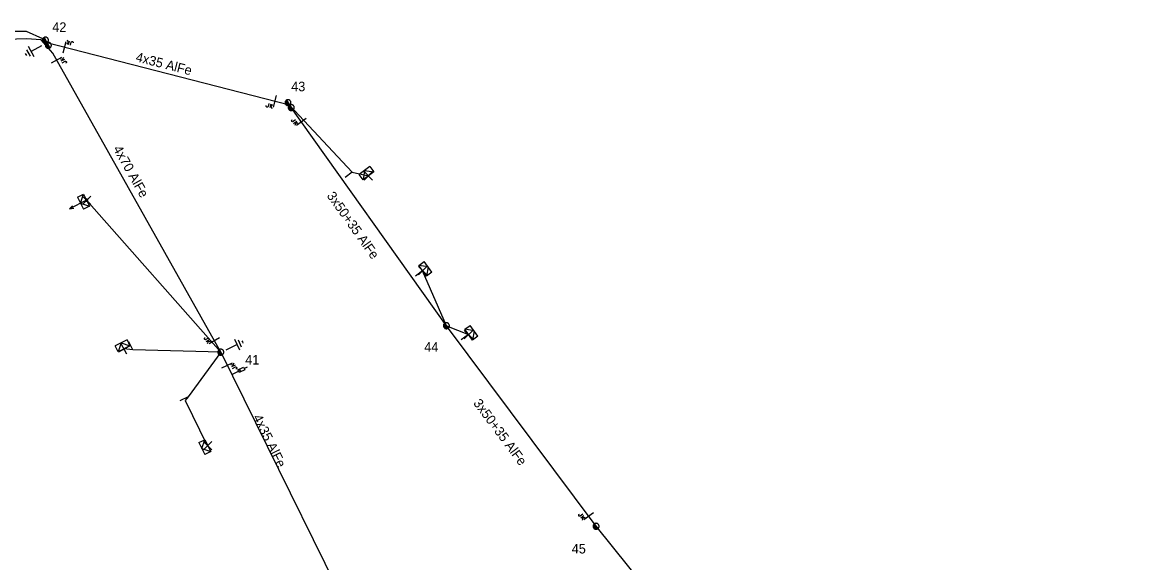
# Model space of a CAD drawing. Extents: x -536148 to -535465, y -1201639 to -1201298.
# Drawn here: x -535725.2 to -535608.3, y -1201357.9 to -1201301.1 of the extents above; entities that cross this region are included whole.
import ezdxf

# ---------------------------------------------------------------- set-up
doc = ezdxf.new("R2010")
doc.units = 0
for name, color, linetype in [('CIZÍ_NADZEM_POPIS', 7, 'Continuous'), ('CIZÍ_PODZEM', 7, 'Continuous'), ('DOPLŇ_POPISY', 7, 'Continuous'), ('ELE_EON', 7, 'Continuous'), ('ELE_EON_POPIS', 7, 'Continuous'), ('KN_HRAN_POHYBLIVÁ', 7, 'Continuous'), ('KN_HRAN_STÁTNÍ', 7, 'Continuous'), ('KN_VKP_HRAN_NEZNATELNÁ', 7, 'Continuous'), ('KN_VKP_HRAN_SPORNÁ', 7, 'Continuous'), ('NADZEM_NN_IZOL_POPIS', 7, 'Continuous'), ('PB_NN_POPIS', 7, 'Continuous'), ('PLG_EXPORT_GPE', 7, 'Continuous'), ('PROJEKT', 7, 'Continuous'), ('RÁMEČEK', 7, 'Continuous')]:
    doc.layers.add(name, color=color, linetype=linetype)

# ---------------------------------------------------------------- blocks, each defined once
blk = doc.blocks.new('NN440')
at = {"layer": 'ELE_EON_POPIS'}
for points in [[(0.63, 0), (0.63, 0.06), (0.62, 0.13), (0.6, 0.19), (0.58, 0.25), (0.55, 0.31), (0.51, 0.37), (0.47, 0.42), (0.42, 0.46), (0.37, 0.51), (0.32, 0.54), (0.26, 0.57), (0.2, 0.59), (0.13, 0.61), (0.07, 0.62), (0, 0.63), (-0.06, 0.62), (-0.13, 0.61), (-0.19, 0.59), (-0.26, 0.57), (-0.31, 0.54), (-0.37, 0.51), (-0.42, 0.46), (-0.47, 0.42), (-0.51, 0.37), (-0.54, 0.31), (-0.57, 0.25), (-0.6, 0.19), (-0.62, 0.13), (-0.63, 0.06), (-0.63, 0), (-0.63, -0.07), (-0.62, -0.14), (-0.6, -0.2), (-0.57, -0.26), (-0.54, -0.32), (-0.51, -0.37), (-0.47, -0.43), (-0.42, -0.47), (-0.37, -0.51), (-0.31, -0.55), (-0.26, -0.58), (-0.19, -0.6), (-0.13, -0.62), (-0.06, -0.63), (0, -0.63), (0.07, -0.63), (0.13, -0.62), (0.2, -0.6), (0.26, -0.58), (0.32, -0.55), (0.37, -0.51), (0.42, -0.47), (0.47, -0.43), (0.51, -0.37), (0.55, -0.32), (0.58, -0.26), (0.6, -0.2), (0.62, -0.14), (0.63, -0.07), (0.63, 0)], [(-0.63, 0), (0.63, 0)], [(-0.6, -0.18), (0.57, -0.18)], [(-0.51, -0.32), (0.5, -0.32)], [(-0.37, -0.47), (0.35, -0.47)]]:
    blk.add_lwpolyline(points, dxfattribs=at)
blk = doc.blocks.new('NN450')
at = {"layer": 'ELE_EON_POPIS'}
for points in [[(0, 0), (0, 0.07), (-0.01, 0.13), (-0.03, 0.19), (-0.05, 0.25), (-0.08, 0.31), (-0.12, 0.37), (-0.16, 0.42), (-0.21, 0.46), (-0.26, 0.51), (-0.31, 0.54), (-0.37, 0.57), (-0.43, 0.59), (-0.5, 0.61), (-0.56, 0.62), (-0.63, 0.62), (-0.69, 0.62), (-0.75, 0.61), (-0.82, 0.59), (-0.88, 0.57), (-0.94, 0.54), (-0.99, 0.51), (-1.04, 0.46), (-1.09, 0.42), (-1.13, 0.37), (-1.17, 0.31), (-1.2, 0.25), (-1.22, 0.19), (-1.24, 0.13), (-1.25, 0.07), (-1.25, 0), (-1.25, -0.07), (-1.24, -0.13), (-1.22, -0.19), (-1.2, -0.25), (-1.17, -0.31), (-1.13, -0.37), (-1.09, -0.42), (-1.04, -0.46), (-0.99, -0.51), (-0.94, -0.54), (-0.88, -0.57), (-0.82, -0.59), (-0.75, -0.61), (-0.69, -0.62), (-0.62, -0.63), (-0.56, -0.62), (-0.5, -0.61), (-0.43, -0.59), (-0.37, -0.57), (-0.31, -0.54), (-0.26, -0.51), (-0.21, -0.46), (-0.16, -0.42), (-0.12, -0.37), (-0.08, -0.31), (-0.05, -0.25), (-0.03, -0.19), (-0.01, -0.13), (0, -0.07), (0, 0)], [(1.25, 0), (1.25, 0.07), (1.24, 0.13), (1.22, 0.19), (1.2, 0.25), (1.17, 0.31), (1.13, 0.37), (1.09, 0.42), (1.04, 0.46), (0.99, 0.51), (0.94, 0.54), (0.88, 0.57), (0.82, 0.59), (0.75, 0.61), (0.69, 0.62), (0.62, 0.62), (0.56, 0.62), (0.5, 0.61), (0.43, 0.59), (0.37, 0.57), (0.31, 0.54), (0.26, 0.51), (0.21, 0.46), (0.16, 0.42), (0.12, 0.37), (0.08, 0.31), (0.05, 0.25), (0.03, 0.19), (0.01, 0.13), (0, 0.07), (0, 0), (0, -0.07), (0.01, -0.13), (0.03, -0.19), (0.05, -0.25), (0.08, -0.31), (0.12, -0.37), (0.16, -0.42), (0.21, -0.46), (0.26, -0.51), (0.31, -0.54), (0.37, -0.57), (0.43, -0.59), (0.5, -0.61), (0.56, -0.62), (0.63, -0.63), (0.69, -0.62), (0.75, -0.61), (0.82, -0.59), (0.88, -0.57), (0.94, -0.54), (0.99, -0.51), (1.04, -0.46), (1.09, -0.42), (1.13, -0.37), (1.17, -0.31), (1.2, -0.25), (1.22, -0.19), (1.24, -0.13), (1.25, -0.07), (1.25, 0)], [(-1.25, 0), (1.25, 0)], [(-1.23, -0.16), (-0.02, -0.16)], [(-1.16, -0.32), (-0.09, -0.32)], [(-1.03, -0.47), (-0.22, -0.47)], [(0.02, -0.16), (1.23, -0.16)], [(0.09, -0.32), (1.16, -0.32)], [(0.22, -0.47), (1.03, -0.47)]]:
    blk.add_lwpolyline(points, dxfattribs=at)
blk = doc.blocks.new('NN560')
at = {"layer": 'ELE_EON_POPIS'}
for points in [[(2, 0), (1.59, 0.14)], [(0, 0), (2, 0)], [(2, 0), (1.59, -0.13)]]:
    blk.add_lwpolyline(points, dxfattribs=at)
blk = doc.blocks.new('NN840')
at = {"layer": 'RÁMEČEK'}
for points in [[(0, 0.62), (0, -0.63)], [(-0.75, -0.71), (-0.75, -0.66)], [(-0.73, -0.76), (-0.75, -0.71)], [(-0.66, -0.8), (-0.73, -0.76)], [(-0.63, -0.8), (-0.66, -0.8)], [(-0.56, -0.76), (-0.63, -0.8)], [(-0.54, -0.71), (-0.56, -0.76)], [(-0.54, -0.38), (-0.54, -0.71)], [(-0.33, -0.38), (-0.33, -0.8)], [(-0.33, -0.64), (-0.13, -0.38)], [(-0.26, -0.56), (-0.09, -0.8)]]:
    blk.add_lwpolyline(points, dxfattribs=at)
blk = doc.blocks.new('NN800')
at = {"layer": 'ELE_EON'}
for points in [[(-0.44, 0.44), (0.44, -0.44)], [(-0.44, -0.44), (0.44, 0.44)]]:
    blk.add_lwpolyline(points, dxfattribs=at)
blk = doc.blocks.new('NN820')
at = {"layer": 'DOPLŇ_POPISY'}
for points in [[(0, 0), (0, -1.05)], [(-0.16, -0.81), (0.16, -0.81)], [(-0.16, -1.47), (-0.16, -0.81)], [(0, -1.05), (-0.06, -0.93)], [(0, -1.05), (0.06, -0.93)], [(0.16, -0.81), (0.16, -1.47)], [(0.16, -1.47), (-0.16, -1.47)], [(0, -1.47), (0, -1.87)]]:
    blk.add_lwpolyline(points, dxfattribs=at)
blk = doc.blocks.new('NN630')
at = {"layer": 'CIZÍ_PODZEM'}
for points in [[(0, -0.7), (-0.7, 0)], [(-0.7, -0.7), (-0.7, 0), (0.7, 0), (0.7, -0.7)], [(-0.7, -0.7), (0.7, -0.7)], [(0, -0.7), (0.7, 0)]]:
    blk.add_lwpolyline(points, dxfattribs=at)
blk = doc.blocks.new('NN810')
at = {"layer": 'PLG_EXPORT_GPE'}
for points in [[(0, -0.64), (0, -1.89)], [(0.63, -1.89), (-0.62, -1.89)], [(0.39, -2.2), (-0.4, -2.2)], [(0, -2.52), (-0.12, -2.52)], [(0.14, -2.52), (0, -2.52)]]:
    blk.add_lwpolyline(points, dxfattribs=at)
blk = doc.blocks.new('NN500')
at = {"layer": 'ELE_EON_POPIS'}
for points in [[(0, -0.24), (0.02, -0.23), (0.05, -0.23), (0.07, -0.22), (0.09, -0.22), (0.12, -0.2), (0.14, -0.19), (0.16, -0.18), (0.17, -0.16), (0.19, -0.14), (0.2, -0.12), (0.21, -0.1), (0.22, -0.07), (0.23, -0.05), (0.23, -0.02), (0.23, 0), (0.23, 0.02), (0.23, 0.05), (0.22, 0.07), (0.21, 0.1), (0.2, 0.12), (0.19, 0.14), (0.17, 0.16), (0.16, 0.17), (0.14, 0.19), (0.12, 0.2), (0.09, 0.21), (0.07, 0.22), (0.05, 0.23), (0.02, 0.23), (0, 0.23), (-0.03, 0.23), (-0.05, 0.23), (-0.07, 0.22), (-0.1, 0.21), (-0.12, 0.2), (-0.14, 0.19), (-0.16, 0.17), (-0.18, 0.16), (-0.19, 0.14), (-0.2, 0.12), (-0.22, 0.1), (-0.22, 0.07), (-0.23, 0.05), (-0.23, 0.02), (-0.24, 0), (-0.23, -0.02), (-0.23, -0.05), (-0.22, -0.07), (-0.22, -0.1), (-0.2, -0.12), (-0.19, -0.14), (-0.18, -0.16), (-0.16, -0.18), (-0.14, -0.19), (-0.12, -0.2), (-0.1, -0.22), (-0.07, -0.22), (-0.05, -0.23), (-0.03, -0.23), (0, -0.24)], [(0, -0.24), (0.02, -0.23), (0.05, -0.23), (0.07, -0.22), (0.09, -0.22), (0.12, -0.2), (0.14, -0.19), (0.16, -0.18), (0.17, -0.16), (0.19, -0.14), (0.2, -0.12), (0.21, -0.1), (0.22, -0.07), (0.23, -0.05), (0.23, -0.02), (0.23, 0), (0.23, 0.02), (0.23, 0.05), (0.22, 0.07), (0.21, 0.1), (0.2, 0.12), (0.19, 0.14), (0.17, 0.16), (0.16, 0.17), (0.14, 0.19), (0.12, 0.2), (0.09, 0.21), (0.07, 0.22), (0.05, 0.23), (0.02, 0.23), (0, 0.23), (-0.03, 0.23), (-0.05, 0.23), (-0.07, 0.22), (-0.1, 0.21), (-0.12, 0.2), (-0.14, 0.19), (-0.16, 0.17), (-0.18, 0.16), (-0.19, 0.14), (-0.2, 0.12), (-0.22, 0.1), (-0.22, 0.07), (-0.23, 0.05), (-0.23, 0.02), (-0.24, 0), (-0.23, -0.02), (-0.23, -0.05), (-0.22, -0.07), (-0.22, -0.1), (-0.2, -0.12), (-0.19, -0.14), (-0.18, -0.16), (-0.16, -0.18), (-0.14, -0.19), (-0.12, -0.2), (-0.1, -0.22), (-0.07, -0.22), (-0.05, -0.23), (-0.03, -0.23), (0, -0.24)], [(0, -0.21), (0.02, -0.2), (0.04, -0.2), (0.06, -0.2), (0.08, -0.19), (0.1, -0.18), (0.12, -0.17), (0.14, -0.15), (0.15, -0.14), (0.16, -0.12), (0.18, -0.1), (0.19, -0.08), (0.19, -0.06), (0.2, -0.04), (0.2, -0.02), (0.2, 0), (0.2, 0.02), (0.2, 0.04), (0.19, 0.06), (0.19, 0.08), (0.18, 0.1), (0.16, 0.12), (0.15, 0.14), (0.14, 0.15), (0.12, 0.17), (0.1, 0.18), (0.08, 0.19), (0.06, 0.19), (0.04, 0.2), (0.02, 0.2), (0, 0.2), (-0.02, 0.2), (-0.04, 0.2), (-0.06, 0.19), (-0.08, 0.19), (-0.1, 0.18), (-0.12, 0.17), (-0.14, 0.15), (-0.15, 0.14), (-0.17, 0.12), (-0.18, 0.1), (-0.19, 0.08), (-0.2, 0.06), (-0.2, 0.04), (-0.21, 0.02), (-0.21, 0), (-0.21, -0.02), (-0.2, -0.04), (-0.2, -0.06), (-0.19, -0.08), (-0.18, -0.1), (-0.17, -0.12), (-0.15, -0.14), (-0.14, -0.15), (-0.12, -0.17), (-0.1, -0.18), (-0.08, -0.19), (-0.06, -0.2), (-0.04, -0.2), (-0.02, -0.2), (0, -0.21)], [(0, -0.18), (0.02, -0.18), (0.04, -0.17), (0.05, -0.17), (0.07, -0.16), (0.09, -0.15), (0.1, -0.14), (0.12, -0.13), (0.13, -0.12), (0.14, -0.1), (0.15, -0.09), (0.16, -0.07), (0.17, -0.05), (0.17, -0.04), (0.17, -0.02), (0.17, 0), (0.17, 0.02), (0.17, 0.04), (0.17, 0.05), (0.16, 0.07), (0.15, 0.09), (0.14, 0.1), (0.13, 0.12), (0.12, 0.13), (0.1, 0.14), (0.09, 0.15), (0.07, 0.16), (0.05, 0.17), (0.04, 0.17), (0.02, 0.17), (0, 0.18), (-0.02, 0.17), (-0.04, 0.17), (-0.06, 0.17), (-0.07, 0.16), (-0.09, 0.15), (-0.1, 0.14), (-0.12, 0.13), (-0.13, 0.12), (-0.14, 0.1), (-0.15, 0.09), (-0.16, 0.07), (-0.17, 0.05), (-0.17, 0.04), (-0.18, 0.02), (-0.18, 0), (-0.18, -0.02), (-0.17, -0.04), (-0.17, -0.05), (-0.16, -0.07), (-0.15, -0.09), (-0.14, -0.1), (-0.13, -0.12), (-0.12, -0.13), (-0.1, -0.14), (-0.09, -0.15), (-0.07, -0.16), (-0.06, -0.17), (-0.04, -0.17), (-0.02, -0.18), (0, -0.18)], [(0, -0.15), (0.01, -0.15), (0.03, -0.14), (0.04, -0.14), (0.06, -0.13), (0.07, -0.13), (0.08, -0.12), (0.1, -0.11), (0.11, -0.1), (0.12, -0.09), (0.13, -0.07), (0.13, -0.06), (0.14, -0.05), (0.14, -0.03), (0.14, -0.02), (0.14, 0), (0.14, 0.01), (0.14, 0.03), (0.14, 0.04), (0.13, 0.06), (0.13, 0.07), (0.12, 0.09), (0.11, 0.1), (0.1, 0.11), (0.08, 0.12), (0.07, 0.13), (0.06, 0.13), (0.04, 0.14), (0.03, 0.14), (0.01, 0.14), (0, 0.15), (-0.02, 0.14), (-0.03, 0.14), (-0.05, 0.14), (-0.06, 0.13), (-0.07, 0.13), (-0.09, 0.12), (-0.1, 0.11), (-0.11, 0.1), (-0.12, 0.09), (-0.13, 0.07), (-0.13, 0.06), (-0.14, 0.04), (-0.14, 0.03), (-0.15, 0.01), (-0.15, 0), (-0.15, -0.02), (-0.14, -0.03), (-0.14, -0.05), (-0.13, -0.06), (-0.13, -0.07), (-0.12, -0.09), (-0.11, -0.1), (-0.1, -0.11), (-0.09, -0.12), (-0.07, -0.13), (-0.06, -0.13), (-0.05, -0.14), (-0.03, -0.14), (-0.02, -0.15), (0, -0.15)], [(0, -0.12), (0.01, -0.12), (0.02, -0.11), (0.03, -0.11), (0.05, -0.11), (0.06, -0.1), (0.07, -0.09), (0.08, -0.09), (0.09, -0.08), (0.09, -0.07), (0.1, -0.06), (0.11, -0.05), (0.11, -0.04), (0.11, -0.02), (0.11, -0.01), (0.12, 0), (0.11, 0.01), (0.11, 0.02), (0.11, 0.04), (0.11, 0.05), (0.1, 0.06), (0.09, 0.07), (0.09, 0.08), (0.08, 0.09), (0.07, 0.09), (0.06, 0.1), (0.05, 0.11), (0.03, 0.11), (0.02, 0.11), (0.01, 0.12), (0, 0.12), (-0.01, 0.12), (-0.03, 0.11), (-0.04, 0.11), (-0.05, 0.11), (-0.06, 0.1), (-0.07, 0.09), (-0.08, 0.09), (-0.09, 0.08), (-0.1, 0.07), (-0.1, 0.06), (-0.11, 0.05), (-0.11, 0.04), (-0.12, 0.02), (-0.12, 0.01), (-0.12, 0), (-0.12, -0.01), (-0.12, -0.02), (-0.11, -0.04), (-0.11, -0.05), (-0.1, -0.06), (-0.1, -0.07), (-0.09, -0.08), (-0.08, -0.09), (-0.07, -0.09), (-0.06, -0.1), (-0.05, -0.11), (-0.04, -0.11), (-0.03, -0.11), (-0.01, -0.12), (0, -0.12)], [(0, -0.09), (0.01, -0.09), (0.02, -0.09), (0.03, -0.08), (0.03, -0.08), (0.04, -0.08), (0.05, -0.07), (0.06, -0.07), (0.06, -0.06), (0.07, -0.05), (0.07, -0.04), (0.08, -0.04), (0.08, -0.03), (0.08, -0.02), (0.09, -0.01), (0.09, 0), (0.09, 0.01), (0.08, 0.02), (0.08, 0.03), (0.08, 0.03), (0.07, 0.04), (0.07, 0.05), (0.06, 0.06), (0.06, 0.06), (0.05, 0.07), (0.04, 0.07), (0.03, 0.08), (0.03, 0.08), (0.02, 0.08), (0.01, 0.09), (0, 0.09), (-0.01, 0.09), (-0.02, 0.08), (-0.03, 0.08), (-0.04, 0.08), (-0.04, 0.07), (-0.05, 0.07), (-0.06, 0.06), (-0.07, 0.06), (-0.07, 0.05), (-0.08, 0.04), (-0.08, 0.03), (-0.08, 0.03), (-0.09, 0.02), (-0.09, 0.01), (-0.09, 0), (-0.09, -0.01), (-0.09, -0.02), (-0.08, -0.03), (-0.08, -0.04), (-0.08, -0.04), (-0.07, -0.05), (-0.07, -0.06), (-0.06, -0.07), (-0.05, -0.07), (-0.04, -0.08), (-0.04, -0.08), (-0.03, -0.08), (-0.02, -0.09), (-0.01, -0.09), (0, -0.09)], [(0, -0.06), (0, -0.06), (0.01, -0.06), (0.02, -0.05), (0.02, -0.05), (0.03, -0.05), (0.03, -0.05), (0.04, -0.04), (0.04, -0.04), (0.05, -0.03), (0.05, -0.03), (0.05, -0.02), (0.05, -0.02), (0.05, -0.01), (0.06, -0.01), (0.06, 0), (0.06, 0.01), (0.05, 0.01), (0.05, 0.02), (0.05, 0.02), (0.05, 0.03), (0.05, 0.03), (0.04, 0.04), (0.04, 0.04), (0.03, 0.05), (0.03, 0.05), (0.02, 0.05), (0.02, 0.05), (0.01, 0.06), (0, 0.06), (0, 0.06), (-0.01, 0.06), (-0.01, 0.06), (-0.02, 0.05), (-0.02, 0.05), (-0.03, 0.05), (-0.03, 0.05), (-0.04, 0.04), (-0.04, 0.04), (-0.05, 0.03), (-0.05, 0.03), (-0.05, 0.02), (-0.06, 0.02), (-0.06, 0.01), (-0.06, 0.01), (-0.06, 0), (-0.06, -0.01), (-0.06, -0.01), (-0.06, -0.02), (-0.05, -0.02), (-0.05, -0.03), (-0.05, -0.03), (-0.04, -0.04), (-0.04, -0.04), (-0.03, -0.05), (-0.03, -0.05), (-0.02, -0.05), (-0.02, -0.05), (-0.01, -0.06), (-0.01, -0.06), (0, -0.06)], [(0, -0.03), (0, -0.03), (0, -0.03), (0.01, -0.03), (0.01, -0.03), (0.01, -0.02), (0.02, -0.02), (0.02, -0.02), (0.02, -0.02), (0.02, -0.02), (0.02, -0.01), (0.02, -0.01), (0.03, -0.01), (0.03, -0.01), (0.03, 0), (0.03, 0), (0.03, 0), (0.03, 0.01), (0.03, 0.01), (0.02, 0.01), (0.02, 0.01), (0.02, 0.02), (0.02, 0.02), (0.02, 0.02), (0.02, 0.02), (0.01, 0.02), (0.01, 0.02), (0.01, 0.03), (0, 0.03), (0, 0.03), (0, 0.03), (0, 0.03), (-0.01, 0.03), (-0.01, 0.03), (-0.01, 0.02), (-0.02, 0.02), (-0.02, 0.02), (-0.02, 0.02), (-0.02, 0.02), (-0.02, 0.02), (-0.03, 0.01), (-0.03, 0.01), (-0.03, 0.01), (-0.03, 0.01), (-0.03, 0), (-0.03, 0), (-0.03, 0), (-0.03, -0.01), (-0.03, -0.01), (-0.03, -0.01), (-0.03, -0.01), (-0.02, -0.02), (-0.02, -0.02), (-0.02, -0.02), (-0.02, -0.02), (-0.02, -0.02), (-0.01, -0.03), (-0.01, -0.03), (-0.01, -0.03), (0, -0.03), (0, -0.03)], [(0.23, 0), (0.7, 0)]]:
    blk.add_lwpolyline(points, dxfattribs=at)
blk = doc.blocks.new('NN510')
at = {"layer": 'ELE_EON_POPIS'}
blk.add_lwpolyline([(0, 0), (0, 0.94)], dxfattribs=at)

msp = doc.modelspace()

# ---------------------------------------------------------------- linework, layer by layer
at = {"layer": 'CIZÍ_NADZEM_POPIS'}
for points in [[(-535704.28, -1201335.78), (-535713.54, -1201335.53), (-535714.46, -1201335.44)], [(-535704.28, -1201335.78), (-535707.73, -1201340.47), (-535708.02, -1201340.86), (-535705.77, -1201345.51), (-535705.65, -1201345.61)]]:
    msp.add_lwpolyline(points, dxfattribs=at)
at = {"layer": 'ELE_EON'}
for points in [[(-535697.05, -1201309.82), (-535722.56, -1201303.26)], [(-535704.28, -1201335.78), (-535721.94, -1201304.37)], [(-535664.84, -1201354.08), (-535680.57, -1201333), (-535697.05, -1201309.82)], [(-535704.28, -1201335.78), (-535687.29, -1201370.27), (-535663.05, -1201399.63), (-535635.32, -1201433.41), (-535614.86, -1201457.77), (-535589.24, -1201487.74), (-535570.26, -1201520.7), (-535562.05, -1201543.24)]]:
    msp.add_lwpolyline(points, dxfattribs=at)
at = {"layer": 'NADZEM_NN_IZOL_POPIS'}
msp.add_lwpolyline([(-535627.8, -1201404.56), (-535635.71, -1201393.75), (-535645.04, -1201380.87), (-535652.14, -1201371.01), (-535656.06, -1201365.68), (-535659.69, -1201360.49), (-535664.84, -1201354.08), (-535664.84, -1201354.08)], dxfattribs=at)
at = {"layer": 'PB_NN_POPIS'}
for points in [[(-535697.05, -1201309.82), (-535690.48, -1201316.88), (-535688.77, -1201317.25)], [(-535704.28, -1201335.78), (-535718.39, -1201319.81)], [(-535680.57, -1201333), (-535683.07, -1201327.23)], [(-535680.57, -1201333), (-535678.25, -1201333.94)]]:
    msp.add_lwpolyline(points, dxfattribs=at)
at = {"layer": 'PROJEKT'}
for points in [[(-535722.56, -1201303.26), (-535722.98, -1201302.84), (-535724.72, -1201302.08), (-535727.05, -1201302.08), (-535730.58, -1201303.91), (-535729.84, -1201305.91), (-535729.81, -1201305.99)], [(-535721.94, -1201304.37), (-535723.15, -1201302.96), (-535724.7, -1201302.86), (-535726.8, -1201302.91), (-535729.94, -1201304.32), (-535729.71, -1201305.86), (-535729.68, -1201305.94)]]:
    msp.add_lwpolyline(points, dxfattribs=at)

# ---------------------------------------------------------------- block references
at = {"layer": 'DOPLŇ_POPISY'}
for name, p, xscale, yscale, rotation in [('NN450', (-535722.56, -1201303.26), 0.5000000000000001, 0.5, -60.70329164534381), ('NN450', (-535697.05, -1201309.82), 0.5, 0.5, -56.92560833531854), ('NN500', (-535718.39, -1201319.81), 0.49999999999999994, 0.5, -153.23499995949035), ('NN440', (-535680.57, -1201333), 0.5, 0.5000000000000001, -53.27259439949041), ('NN440', (-535704.28, -1201335.78), 0.5000000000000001, 0.5, -63.8193083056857), ('NN440', (-535664.84, -1201354.08), 0.49999999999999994, 0.5000000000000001, -51.207491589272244)]:
    msp.add_blockref(name, p, dxfattribs=dict(at, xscale=xscale, yscale=yscale, rotation=rotation))
for name, p, rotation in [('NN510', (-535690.47, -1201316.88), 126.12148895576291), ('NN560', (-535718.39, -1201319.81), -153.27410561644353), ('NN510', (-535683.07, -1201327.23), 126.2071916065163), ('NN510', (-535678.24, -1201333.94), 125.6026861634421), ('NN510', (-535713.54, -1201335.53), 26.25728886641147), ('NN510', (-535707.73, -1201340.47), 116.07314170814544)]:
    msp.add_blockref(name, p, dxfattribs=dict(at, rotation=rotation))
at = {"layer": 'KN_HRAN_POHYBLIVÁ'}
for p, rotation in [((-535720.7, -1201303.74), 165.55157766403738), ((-535721.54, -1201305.08), 119.4915888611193), ((-535698.62, -1201309.42), -14.41305004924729), ((-535695.8, -1201311.58), -54.55930825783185), ((-535704.97, -1201334.59), -60.572613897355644), ((-535703.62, -1201337.17), 116.22331942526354), ((-535665.62, -1201353.03), -53.27303885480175)]:
    msp.add_blockref('NN840', p, dxfattribs=dict(at, rotation=rotation))
at = {"layer": 'KN_HRAN_STÁTNÍ', "rotation": 116.25315000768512}
msp.add_blockref('NN820', (-535703.14, -1201338.14), dxfattribs=at)
at = {"layer": 'KN_VKP_HRAN_NEZNATELNÁ'}
for p in [(-535688.77, -1201317.25), (-535718.39, -1201319.81), (-535683.07, -1201327.23), (-535678.25, -1201333.94), (-535705.65, -1201345.61)]:
    msp.add_blockref('NN800', p, dxfattribs=at)
at = {"layer": 'KN_VKP_HRAN_NEZNATELNÁ', "rotation": 73.12296663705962}
msp.add_blockref('NN800', (-535714.46, -1201335.44), dxfattribs=at)
at = {"layer": 'KN_VKP_HRAN_SPORNÁ'}
for p, rotation in [((-535688.77, -1201317.25), -143.8311750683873), ((-535718.39, -1201319.81), -63.27828332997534), ((-535683.07, -1201327.23), 126.21445003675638), ((-535678.24, -1201333.94), 125.58795275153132), ((-535714.46, -1201335.44), -153.7736972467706), ((-535705.65, -1201345.61), -63.849822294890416)]:
    msp.add_blockref('NN630', p, dxfattribs=dict(at, rotation=rotation))
at = {"layer": 'RÁMEČEK'}
for p, rotation in [((-535722.56, -1201303.26), -60.57565824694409), ((-535704.29, -1201335.8), 115.58682774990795)]:
    msp.add_blockref('NN810', p, dxfattribs=dict(at, rotation=rotation))

# ---------------------------------------------------------------- texts
at = {"layer": 'ELE_EON_POPIS'}
for s, rotation, p in [('4x35 AlFe', 345.579, (-535713.3, -1201305.2)), ('4x70 AlFe', 299.349, (-535715.64, -1201314.4)), ('3x50+35 AlFe', 305.415, (-535693.19, -1201319.35)), ('3x50+35 AlFe', 306.727, (-535677.8, -1201341.15)), ('4x35 AlFe', 296.225, (-535700.94, -1201342.62))]:
    msp.add_text(s, height=1, rotation=rotation, dxfattribs=at).set_placement(p)
at = {"layer": 'PLG_EXPORT_GPE'}
for s, p in [('42', (-535722, -1201302.12)), ('43', (-535696.89, -1201308.36)), ('44', (-535682.9, -1201335.73)), ('41', (-535701.72, -1201337.08)), ('45', (-535667.4, -1201356.94))]:
    msp.add_text(s, height=1, dxfattribs=at).set_placement(p)

doc.saveas('drawing.dxf')
